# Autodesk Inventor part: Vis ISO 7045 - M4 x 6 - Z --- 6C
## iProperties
Created: 2011-01
Part Number: Vis ISO 7045 - M4 x 6 - Z --- 6C
Document SubType Name: Modeling
Designer: eric
Density: 1 g/cm^3
Mass: 0.18578 g
Surface Area: 2.44568 cm^2
Volume: 0.18578 cm^3
Author: eric
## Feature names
1. Base1
